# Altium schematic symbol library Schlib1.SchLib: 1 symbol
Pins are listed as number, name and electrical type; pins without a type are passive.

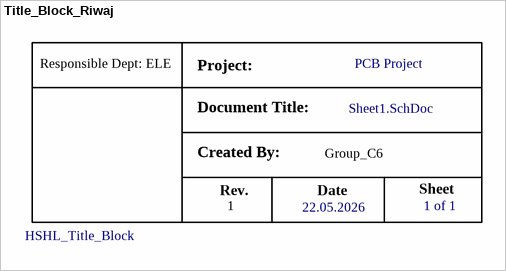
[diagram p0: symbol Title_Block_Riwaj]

## Title_Block_Riwaj
designator *, comment HSHL_Title_Block  (graphical)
